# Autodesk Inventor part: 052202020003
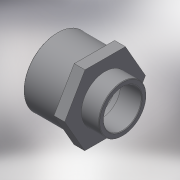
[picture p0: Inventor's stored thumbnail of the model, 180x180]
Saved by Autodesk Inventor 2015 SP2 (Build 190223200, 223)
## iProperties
Created: 2017-10
Part Number: 052202020003
Material: Generic
Description: PLASSON BUSHING ADAP. THR-CEM 20(25)-3/8"
Document SubType Name: Modeling
Designer: KIM
Density: 1 g/cm^3
Appearance: Default
Author: KIM
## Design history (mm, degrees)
derived "052202.ipt"
feature "Solid1::052202.ipt"
tag "TaggingFeature1"
body "Solid1"
other parameters: "d0" = 42, "d13" = 0, "d14" = 0.2, "d17" = 19, "d18" = 13.2, "d19" = 25, "d21" = 16.662, "d22" = 16, "d23" = 19, "d24" = 13.3296, "d25" = 11, "d26" = -19, "R_" = 16.662, "B_" = 12, "L_" = 19, "lt_" = 11, "H_" = 42, "D_" = 25, "l_" = 16
